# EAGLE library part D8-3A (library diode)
4 DIODES SIL, anode marked
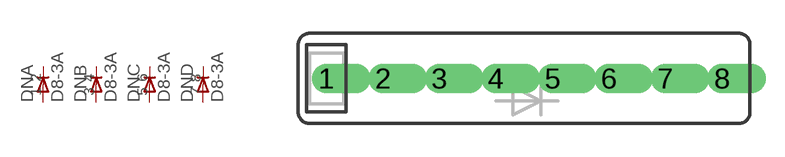
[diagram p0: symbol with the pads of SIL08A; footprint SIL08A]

Designator prefix DN; gates A=DN B=DN C=DN D=DN

## D8-3A  [SIL08A]
1  A:A  pas
2  A:C  pas
3  B:A  pas
4  B:C  pas
5  C:A  pas
6  C:C  pas
7  D:A  pas
8  D:C  pas

## Footprint SIL08A (pad centres in mm)
7 DIODES single in line 7 diodes with common anode
drill 0.813 offset: 1 -8.89,0; 2 -6.35,0; 3 -3.81,0; 4 -1.27,0; 5 1.27,0; 6 3.81,0; 7 6.35,0; 8 8.89,0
